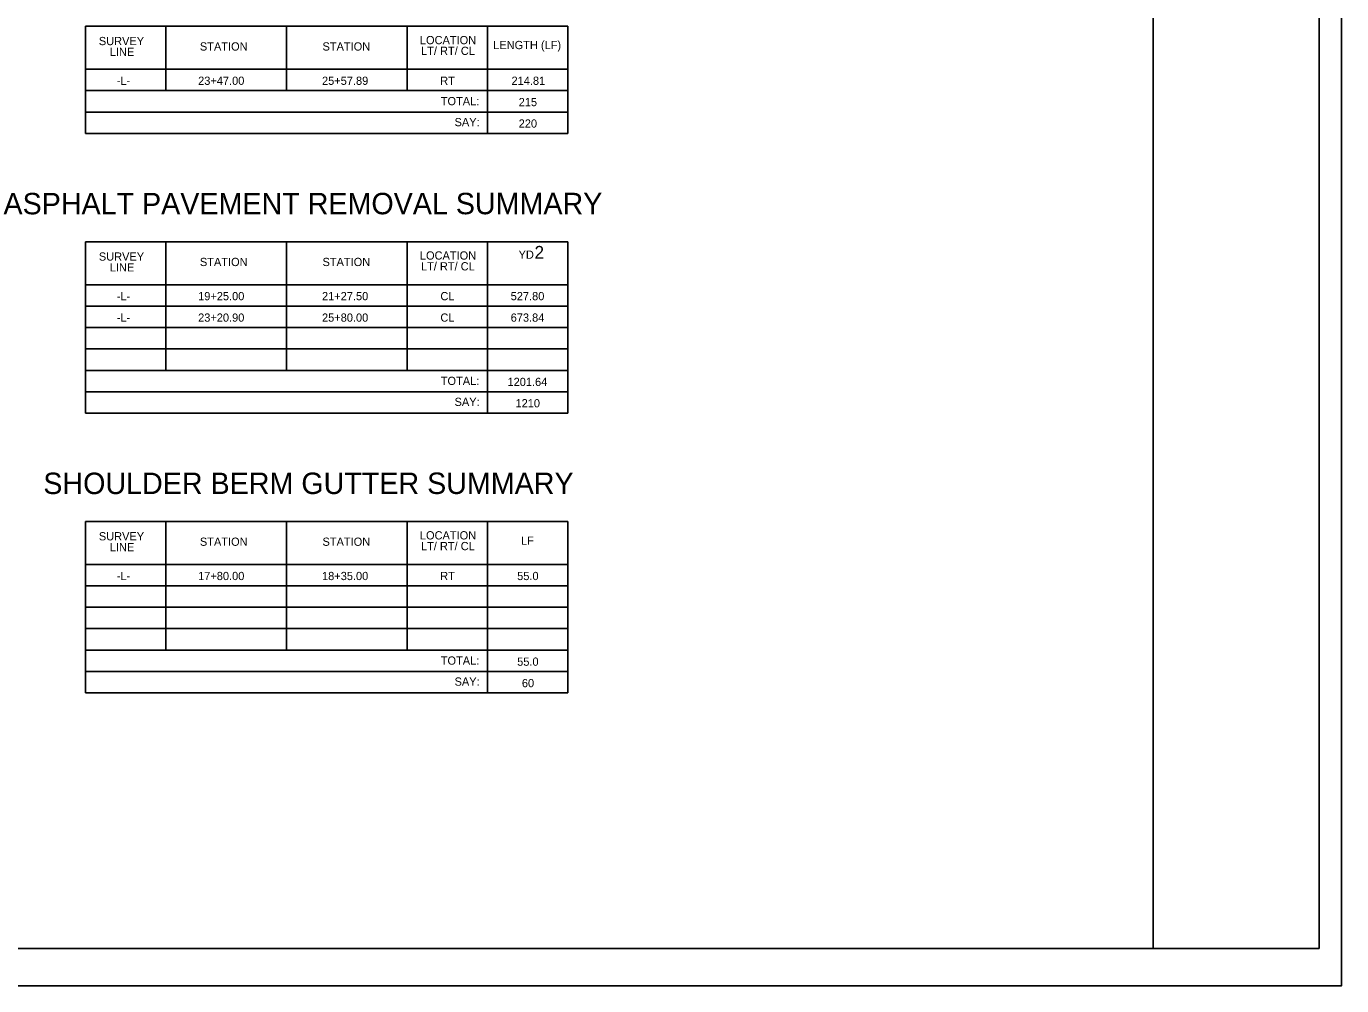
# Model space of a CAD drawing. Extents: x 1184121 to 1184360, y 1246506 to 1246661.
# Drawn here: x 1184248.8 to 1184360.3, y 1246505.7 to 1246587.1 of the extents above; entities that cross this region are included whole.
import ezdxf

# ---------------------------------------------------------------- set-up
doc = ezdxf.new("R2010")
doc.units = 0
for name, color, linetype in [('Sheet Data Field CELL', 7, 'Continuous'), ('Sheet Plan CELL', 7, 'Continuous'), ('Sheet Plot Border Outside CELL', 7, 'Continuous'), ('z - Construction', 7, 'Continuous')]:
    doc.layers.add(name, color=color, linetype=linetype)

msp = doc.modelspace()

# ---------------------------------------------------------------- linework, layer by layer
at = {"layer": 'Sheet Data Field CELL'}
for p, q in [((1184253.78, 1246587.13), (1184294.7, 1246587.13)), ((1184253.78, 1246587.13), (1184253.78, 1246578.04)), ((1184260.6, 1246587.13), (1184260.6, 1246581.67)), ((1184270.83, 1246587.13), (1184270.83, 1246581.67)), ((1184274.32, 1246587.12), (1184274.32, 1246587.12)), ((1184275.23, 1246587.1), (1184275.23, 1246587.1)), ((1184277.36, 1246587.12), (1184277.36, 1246587.12)), ((1184281.06, 1246587.13), (1184281.06, 1246581.67)), ((1184287.88, 1246587.13), (1184287.88, 1246578.04)), ((1184294.7, 1246587.13), (1184294.7, 1246578.04)), ((1184253.78, 1246583.49), (1184294.7, 1246583.49)), ((1184253.78, 1246581.67), (1184294.7, 1246581.67)), ((1184253.78, 1246581.67), (1184294.7, 1246581.67)), ((1184253.78, 1246579.85), (1184294.7, 1246579.85)), ((1184253.78, 1246578.04), (1184294.7, 1246578.04)), ((1184253.78, 1246568.84), (1184294.7, 1246568.84)), ((1184253.78, 1246568.84), (1184253.78, 1246554.29)), ((1184260.6, 1246568.84), (1184260.6, 1246557.93)), ((1184270.83, 1246568.84), (1184270.83, 1246557.93)), ((1184274.32, 1246568.83), (1184274.32, 1246568.83)), ((1184275.23, 1246568.82), (1184275.23, 1246568.82)), ((1184276.55, 1246568.85), (1184276.55, 1246568.85)), ((1184277.36, 1246568.83), (1184277.36, 1246568.83)), ((1184281.06, 1246568.84), (1184281.06, 1246557.93)), ((1184287.88, 1246568.84), (1184287.88, 1246554.29)), ((1184294.7, 1246568.84), (1184294.7, 1246554.29)), ((1184253.78, 1246565.2), (1184294.7, 1246565.2)), ((1184253.78, 1246563.38), (1184294.7, 1246563.38)), ((1184253.78, 1246561.57), (1184294.7, 1246561.57)), ((1184253.78, 1246559.75), (1184294.7, 1246559.75)), ((1184253.78, 1246557.93), (1184294.7, 1246557.93)), ((1184253.78, 1246556.11), (1184294.7, 1246556.11)), ((1184253.78, 1246554.29), (1184294.7, 1246554.29)), ((1184253.78, 1246545.1), (1184294.7, 1246545.1)), ((1184253.78, 1246545.1), (1184253.78, 1246530.55)), ((1184260.6, 1246545.1), (1184260.6, 1246534.19)), ((1184270.83, 1246545.1), (1184270.83, 1246534.19)), ((1184274.32, 1246545.09), (1184274.32, 1246545.09)), ((1184275.23, 1246545.08), (1184275.23, 1246545.08)), ((1184276.55, 1246545.1), (1184276.55, 1246545.1)), ((1184277.36, 1246545.09), (1184277.36, 1246545.09)), ((1184281.06, 1246545.1), (1184281.06, 1246534.19)), ((1184287.88, 1246545.1), (1184287.88, 1246530.55)), ((1184294.7, 1246545.1), (1184294.7, 1246530.55)), ((1184253.78, 1246541.46), (1184294.7, 1246541.46)), ((1184253.78, 1246539.64), (1184294.7, 1246539.64)), ((1184253.78, 1246537.82), (1184294.7, 1246537.82)), ((1184253.78, 1246536.01), (1184294.7, 1246536.01)), ((1184253.78, 1246534.19), (1184294.7, 1246534.19)), ((1184253.78, 1246532.37), (1184294.7, 1246532.37)), ((1184253.78, 1246530.55), (1184294.7, 1246530.55))]:
    msp.add_line(p, q, dxfattribs=at)
at = {"layer": 'Sheet Plan CELL'}
for p, q in [((1184344.34, 1246508.87), (1184344.35, 1246657.36)), ((1184358.42, 1246508.87), (1184358.42, 1246657.36)), ((1184126.18, 1246508.87), (1184358.42, 1246508.87))]:
    msp.add_line(p, q, dxfattribs=at)
at = {"layer": 'Sheet Plot Border Outside CELL'}
msp.add_lwpolyline([(1184121.05, 1246660.53), (1184360.32, 1246660.53), (1184360.32, 1246505.71), (1184121.05, 1246505.71)], close=True, dxfattribs=at)
at = {"layer": 'z - Construction'}
for p, q in [((1184360.32, 1246505.71), (1184360.32, 1246660.53)), ((1184121.05, 1246505.71), (1184360.32, 1246505.71))]:
    msp.add_line(p, q, dxfattribs=at)

# ---------------------------------------------------------------- texts
at = {"layer": 'Sheet Data Field CELL'}
for s, height, p in [('SURVEY', 0.698, (1184254.91, 1246585.53)), ('LOCATION', 0.698, (1184282.14, 1246585.61)), ('LENGTH (LF)', 0.6981, (1184288.36, 1246585.19)), ('LINE', 0.698, (1184255.84, 1246584.61)), ('STATION', 0.698, (1184263.48, 1246585.07)), ('STATION', 0.698, (1184273.88, 1246585.07)), ('LT/ RT/ CL', 0.698, (1184282.24, 1246584.7)), ('-L-', 0.698, (1184256.43, 1246582.16)), ('23+47.00', 0.698, (1184263.33, 1246582.16)), ('25+57.89', 0.698, (1184273.84, 1246582.16)), ('RT', 0.698, (1184283.86, 1246582.16)), ('214.81', 0.698, (1184289.91, 1246582.16)), ('TOTAL:', 0.698, (1184283.91, 1246580.43)), ('215', 0.698, (1184290.52, 1246580.35)), ('SAY:', 0.698, (1184285.08, 1246578.65)), ('220', 0.698, (1184290.52, 1246578.53)), ('LOCATION', 0.698, (1184282.14, 1246567.33)), ('YD', 0.698, (1184290.51, 1246567.4)), ('2', 1.09, (1184291.86, 1246567.4)), ('SURVEY', 0.698, (1184254.91, 1246567.24)), ('LINE', 0.698, (1184255.84, 1246566.32)), ('STATION', 0.698, (1184263.48, 1246566.78)), ('STATION', 0.698, (1184273.88, 1246566.78)), ('LT/ RT/ CL', 0.698, (1184282.23, 1246566.41)), ('-L-', 0.698, (1184256.43, 1246563.88)), ('19+25.00', 0.698, (1184263.33, 1246563.88)), ('21+27.50', 0.698, (1184273.84, 1246563.88)), ('CL', 0.698, (1184283.88, 1246563.88)), ('527.80', 0.698, (1184289.84, 1246563.88)), ('-L-', 0.698, (1184256.43, 1246562.06)), ('23+20.90', 0.698, (1184263.33, 1246562.06)), ('25+80.00', 0.698, (1184273.84, 1246562.06)), ('CL', 0.698, (1184283.88, 1246562.06)), ('673.84', 0.698, (1184289.84, 1246562.06)), ('TOTAL:', 0.698, (1184283.91, 1246556.69)), ('1201.64', 0.698, (1184289.57, 1246556.6)), ('SAY:', 0.698, (1184285.08, 1246554.91)), ('1210', 0.698, (1184290.25, 1246554.79)), ('SURVEY', 0.698, (1184254.91, 1246543.5)), ('STATION', 0.698, (1184263.48, 1246543.04)), ('STATION', 0.698, (1184273.88, 1246543.04)), ('LOCATION', 0.698, (1184282.14, 1246543.58)), ('LF', 0.698, (1184290.72, 1246543.13)), ('LINE', 0.698, (1184255.84, 1246542.58)), ('LT/ RT/ CL', 0.698, (1184282.23, 1246542.67)), ('-L-', 0.698, (1184256.43, 1246540.13)), ('17+80.00', 0.698, (1184263.33, 1246540.13)), ('18+35.00', 0.698, (1184273.84, 1246540.13)), ('RT', 0.698, (1184283.86, 1246540.13)), ('55.0', 0.698, (1184290.39, 1246540.13)), ('TOTAL:', 0.698, (1184283.91, 1246532.95)), ('55.0', 0.698, (1184290.39, 1246532.86)), ('SAY:', 0.698, (1184285.08, 1246531.17)), ('60', 0.698, (1184290.79, 1246531.04))]:
    msp.add_text(s, height=height, dxfattribs=at).set_placement(p)
for s, p in [('ASPHALT PAVEMENT REMOVAL SUMMARY', (1184246.82, 1246571.17)), ('SHOULDER BERM GUTTER SUMMARY', (1184250.2, 1246547.43))]:
    msp.add_text(s, height=1.818, rotation=0.0119, dxfattribs=at).set_placement(p)

doc.saveas('drawing.dxf')
